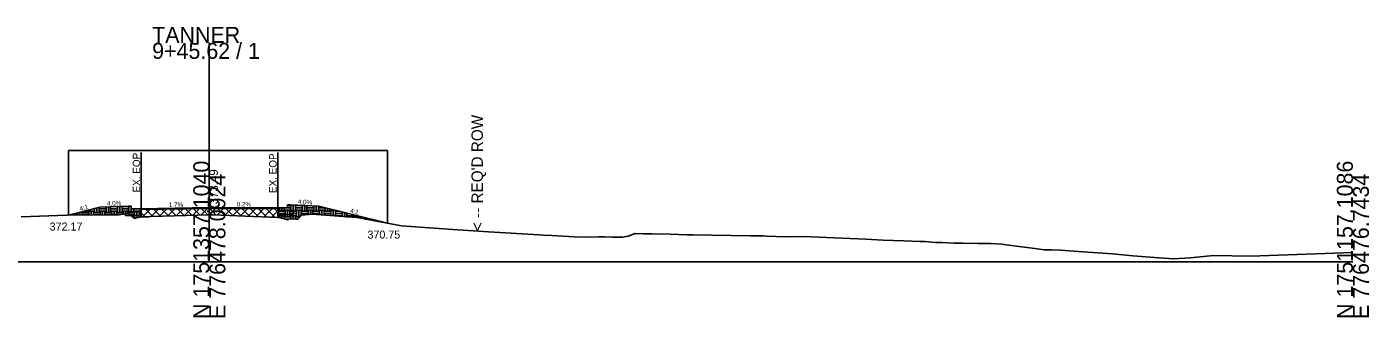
# Model space of a CAD drawing. Extents: x 774192 to 776597, y 1750236 to 1752784.
# Drawn here: x 774851.4 to 775086.2, y 1752248.9 to 1752299.7 of the extents above; entities that cross this region are included whole.
import ezdxf

# ---------------------------------------------------------------- set-up
doc = ezdxf.new("R2010")
doc.units = 0
for name, color, linetype in [('ControlPoints', 7, 'Continuous'), ('Default', 7, 'Continuous'), ('Observations', 7, 'Continuous'), ('Setups', 7, 'Continuous'), ('SHEET_BORDER_TX', 7, 'Continuous'), ('SHEET_DATE_DGN_TX', 7, 'Continuous'), ('SHEET_LOGO', 7, 'Continuous'), ('SHEET_PLOTTING_SHAPE', 7, 'Continuous'), ('SHEET_PRELIM', 7, 'Continuous'), ('SHEET_PROJ_NUMBER', 7, 'Continuous'), ('SHEET_TITLE_BLOCK_TX', 7, 'Continuous'), ('SHEET_WORK_NUMBER', 7, 'Continuous'), ('TS_BACKBONE', 7, 'Continuous'), ('TS_DIMENSIONS', 7, 'Continuous')]:
    doc.layers.add(name, color=color, linetype=linetype)

msp = doc.modelspace()

# ---------------------------------------------------------------- linework, layer by layer
at = {"layer": 'ControlPoints'}
msp.add_lwpolyline([(774850.41, 1752266.46), (774858.47, 1752266.74), (774865.85, 1752266.76), (774867.52, 1752266.78), (774869.22, 1752267.02), (774870.21, 1752266.17), (774871.43, 1752266.43), (774872.71, 1752266.42), (774873.08, 1752266.52), (774883.33, 1752266.76), (774884.02, 1752266.78), (774895.29, 1752266.33), (774895.62, 1752266.32), (774897.13, 1752265.93), (774897.32, 1752266.11), (774898.78, 1752266.03), (774899.42, 1752266.71), (774901.3, 1752266.88), (774909.14, 1752266.3), (774909.18, 1752266.3), (774916.94, 1752264.88), (774922.66, 1752264.44), (774925.93, 1752264.21), (774929.53, 1752263.97), (774932.17, 1752263.84), (774941.04, 1752263.29), (774941.76, 1752263.24), (774943.26, 1752263.18), (774946.18, 1752262.99), (774947.13, 1752262.95), (774949.77, 1752262.89), (774951.45, 1752262.91), (774952.46, 1752262.91), (774953.84, 1752262.9), (774955.55, 1752262.85), (774956.56, 1752263.08), (774957.8, 1752263.51), (774959.24, 1752263.49), (774960.13, 1752263.47), (774960.72, 1752263.46), (774963.93, 1752263.39), (774966.91, 1752263.28), (774967.89, 1752263.27), (774977.89, 1752263.1), (774979.19, 1752263.09), (774980.23, 1752263.09), (774980.8, 1752263.03), (774984.19, 1752262.95), (774987.16, 1752263), (774998.16, 1752262.54), (774999.12, 1752262.48), (775001.19, 1752262.36), (775004.81, 1752262.25), (775007.6, 1752262.13), (775008.5, 1752262.13), (775010.3, 1752261.93), (775011.44, 1752261.93), (775012.46, 1752261.88), (775013.59, 1752261.85), (775015.16, 1752261.82), (775017.82, 1752261.75), (775020.02, 1752261.75), (775021.97, 1752261.64), (775022.28, 1752261.6), (775022.71, 1752261.55), (775027.7, 1752260.9), (775029.35, 1752260.69), (775030.08, 1752260.66), (775030.6, 1752260.65), (775032.23, 1752260.6), (775035.28, 1752260.35), (775041.3, 1752259.95), (775044.86, 1752259.62), (775049.41, 1752259.26), (775052.01, 1752259.08), (775054.85, 1752259.29), (775058.95, 1752259.68), (775065.45, 1752259.56), (775083.33, 1752260.21)], dxfattribs=at)
at = {"layer": 'Default'}
for p, q in [((774871.33, 1752267.69), (774883.34, 1752267.89)), ((774883.33, 1752267.89), (774895.33, 1752267.86))]:
    msp.add_line(p, q, dxfattribs=at)
at = {"layer": 'Setups'}
for p, q in [((774883.33, 1752258.57), (774883.33, 1752296.88)), ((774683.33, 1752258.57), (774883.33, 1752258.57)), ((774883.33, 1752258.57), (775083.33, 1752258.57))]:
    msp.add_line(p, q, dxfattribs=at)
at = {"layer": 'SHEET_BORDER_TX'}
for p, q in [((774868.67, 1752266.64), (774868.67, 1752267.31)), ((774898, 1752266.86), (774898, 1752267.53)), ((774871.35, 1752266.69), (774868.67, 1752266.64)), ((774895.33, 1752266.86), (774898, 1752266.86))]:
    msp.add_line(p, q, dxfattribs=at)
for points in [[(774868.67, 1752267.31), (774871.33, 1752267.35), (774871.35, 1752266.69)], [(774898, 1752267.53), (774895.33, 1752267.53), (774895.33, 1752266.86)]]:
    msp.add_lwpolyline(points, dxfattribs=at)
at = {"layer": 'SHEET_LOGO'}
for p, q in [((774871.43, 1752277.71), (774871.43, 1752266.43)), ((774895.29, 1752277.71), (774895.29, 1752266.33))]:
    msp.add_line(p, q, dxfattribs=at)
at = {"layer": 'SHEET_PLOTTING_SHAPE'}
for p, q in [((774869.17, 1752267.32), (774869.17, 1752268.32)), ((774871.33, 1752267.35), (774869.17, 1752267.32)), ((774871.33, 1752267.85), (774871.33, 1752267.35)), ((774895.33, 1752268.03), (774895.33, 1752267.53)), ((774895.33, 1752267.53), (774897.5, 1752267.53)), ((774897.5, 1752267.53), (774897.5, 1752268.53))]:
    msp.add_line(p, q, dxfattribs=at)
at = {"layer": 'SHEET_PROJ_NUMBER'}
for p, q in [((774858.68, 1752266.74), (774858.68, 1752278.06)), ((774858.68, 1752278.06), (774914.5, 1752278.06)), ((774914.5, 1752278.06), (774914.5, 1752265.33))]:
    msp.add_line(p, q, dxfattribs=at)
at = {"layer": 'SHEET_TITLE_BLOCK_TX'}
for p, q in [((774864.17, 1752268.12), (774858.68, 1752266.74)), ((774869.17, 1752268.32), (774864.17, 1752268.12)), ((774869.67, 1752268.33), (774869.17, 1752268.32)), ((774869.67, 1752267.83), (774869.67, 1752268.33)), ((774871.33, 1752267.85), (774869.67, 1752267.83)), ((774871.33, 1752267.85), (774883.33, 1752268.06)), ((774883.33, 1752268.06), (774895.33, 1752268.03)), ((774895.33, 1752268.03), (774897, 1752268.03)), ((774897, 1752268.03), (774897, 1752268.53)), ((774897, 1752268.53), (774897.5, 1752268.53)), ((774897.5, 1752268.53), (774902.5, 1752268.33)), ((774902.5, 1752268.33), (774914.5, 1752265.33))]:
    msp.add_line(p, q, dxfattribs=at)
at = {"layer": 'SHEET_WORK_NUMBER'}
for p, q in [((774871.33, 1752267.35), (774871.33, 1752266.41)), ((774895.33, 1752267.53), (774895.33, 1752266.33))]:
    msp.add_line(p, q, dxfattribs=at)
msp.add_lwpolyline([(774871.33, 1752266.41), (774871.43, 1752266.43), (774872.71, 1752266.42), (774873.08, 1752266.52), (774883.33, 1752266.76), (774884.02, 1752266.78), (774895.33, 1752266.33)], dxfattribs=at)
at = {"layer": 'TS_BACKBONE'}
for p, q in [((774860.27, 1752267.14), (774860.27, 1752266.75)), ((774860.67, 1752267.24), (774860.67, 1752266.75)), ((774861.07, 1752267.32), (774861.07, 1752266.75)), ((774861.17, 1752267.22), (774862.17, 1752267.22)), ((774861.27, 1752267.39), (774861.27, 1752267.32)), ((774861.67, 1752267.49), (774861.67, 1752267.32)), ((774862.07, 1752267.59), (774862.07, 1752267.32)), ((774862.17, 1752267.42), (774863.17, 1752267.42)), ((774862.27, 1752267.32), (774862.27, 1752266.75)), ((774862.67, 1752267.32), (774862.67, 1752266.75)), ((774863, 1752267.82), (774863.17, 1752267.82)), ((774863.07, 1752267.32), (774863.07, 1752266.75)), ((774863.17, 1752267.22), (774864.17, 1752267.22)), ((774863.27, 1752267.89), (774863.27, 1752267.32)), ((774863.67, 1752267.99), (774863.67, 1752267.32)), ((774864.07, 1752268.09), (774864.07, 1752267.32)), ((774864.17, 1752267.82), (774865.17, 1752267.82)), ((774864.17, 1752267.42), (774865.17, 1752267.42)), ((774864.27, 1752267.32), (774864.27, 1752266.75)), ((774864.67, 1752267.32), (774864.67, 1752266.75)), ((774865.07, 1752267.32), (774865.07, 1752266.76)), ((774865.17, 1752267.22), (774866.17, 1752267.22)), ((774865.27, 1752268.16), (774865.27, 1752267.32)), ((774865.67, 1752268.18), (774865.67, 1752267.32)), ((774866.07, 1752268.19), (774866.07, 1752267.32)), ((774866.17, 1752267.82), (774867.17, 1752267.82)), ((774866.17, 1752267.42), (774867.17, 1752267.42)), ((774866.27, 1752267.32), (774866.27, 1752266.76)), ((774866.67, 1752267.32), (774866.67, 1752266.77)), ((774866.84, 1752268.22), (774867.17, 1752268.22)), ((774867.07, 1752267.32), (774867.07, 1752266.77)), ((774867.17, 1752267.22), (774868.17, 1752267.22)), ((774867.27, 1752268.24), (774867.27, 1752267.32)), ((774867.67, 1752268.26), (774867.67, 1752267.32)), ((774868.07, 1752268.27), (774868.07, 1752267.32)), ((774868.17, 1752268.22), (774869.17, 1752268.22)), ((774868.17, 1752267.82), (774869.17, 1752267.82)), ((774868.17, 1752267.42), (774869.17, 1752267.42)), ((774868.27, 1752267.32), (774868.27, 1752266.89)), ((774868.67, 1752267.32), (774868.67, 1752266.94)), ((774869.07, 1752267.32), (774869.07, 1752267)), ((774869.17, 1752267.22), (774870.17, 1752267.22)), ((774869.27, 1752268.32), (774869.27, 1752267.32)), ((774869.27, 1752267.32), (774869.27, 1752267.32)), ((774869.67, 1752267.83), (774869.67, 1752267.33)), ((774869.67, 1752267.33), (774869.67, 1752267.32)), ((774870.07, 1752267.83), (774870.07, 1752267.33)), ((774870.07, 1752267.33), (774870.07, 1752267.32)), ((774870.17, 1752267.82), (774871.17, 1752267.82)), ((774870.17, 1752267.42), (774871.17, 1752267.42)), ((774870.27, 1752267.32), (774870.27, 1752266.32)), ((774870.67, 1752267.32), (774870.67, 1752266.32)), ((774871.07, 1752267.32), (774871.07, 1752266.36)), ((774871.17, 1752267.22), (774871.33, 1752267.22)), ((774871.27, 1752267.85), (774871.27, 1752267.35)), ((774871.27, 1752267.35), (774871.27, 1752267.32)), ((774871.33, 1752267.52), (774871.67, 1752267.86)), ((774871.33, 1752267.19), (774872.09, 1752266.43)), ((774871.66, 1752266.43), (774873.11, 1752267.88)), ((774872.07, 1752267.87), (774873.41, 1752266.53)), ((774873.17, 1752266.52), (774874.55, 1752267.91)), ((774873.46, 1752267.89), (774874.79, 1752266.56)), ((774874.62, 1752266.56), (774875.99, 1752267.93)), ((774874.85, 1752267.91), (774876.17, 1752266.59)), ((774876.06, 1752266.59), (774877.43, 1752267.96)), ((774876.24, 1752267.94), (774877.55, 1752266.63)), ((774877.51, 1752266.63), (774878.87, 1752267.98)), ((774877.63, 1752267.96), (774878.93, 1752266.66)), ((774878.96, 1752266.66), (774880.31, 1752268.01)), ((774879.02, 1752267.98), (774880.32, 1752266.69)), ((774880.41, 1752266.69), (774881.74, 1752268.03)), ((774880.41, 1752268.01), (774881.7, 1752266.72)), ((774881.8, 1752268.03), (774883.08, 1752266.76)), ((774881.86, 1752266.73), (774883.18, 1752268.06)), ((774883.19, 1752268.06), (774884.49, 1752266.76)), ((774883.3, 1752266.76), (774884.6, 1752268.06)), ((774884.61, 1752268.06), (774885.96, 1752266.7)), ((774884.71, 1752266.75), (774886.01, 1752268.05)), ((774886.03, 1752268.05), (774887.44, 1752266.64)), ((774886.07, 1752266.7), (774887.42, 1752268.05)), ((774887.43, 1752266.64), (774888.83, 1752268.05)), ((774887.44, 1752268.05), (774888.91, 1752266.59)), ((774888.79, 1752266.59), (774890.24, 1752268.04)), ((774888.86, 1752268.05), (774890.38, 1752266.53)), ((774890.15, 1752266.54), (774891.65, 1752268.04)), ((774890.28, 1752268.04), (774891.85, 1752266.47)), ((774891.51, 1752266.48), (774893.06, 1752268.04)), ((774891.7, 1752268.04), (774893.32, 1752266.41)), ((774892.87, 1752266.43), (774894.48, 1752268.03)), ((774893.11, 1752268.04), (774894.8, 1752266.35)), ((774894.23, 1752266.38), (774895.33, 1752267.48)), ((774894.53, 1752268.03), (774895.33, 1752267.23)), ((774895.33, 1752267.63), (774895.5, 1752267.63)), ((774895.4, 1752267.53), (774895.4, 1752267.53)), ((774895.4, 1752267.53), (774895.4, 1752266.53)), ((774895.5, 1752267.43), (774896.5, 1752267.43)), ((774895.61, 1752268.03), (774895.61, 1752267.53)), ((774895.61, 1752267.53), (774895.61, 1752267.53)), ((774896.01, 1752268.03), (774896.01, 1752267.53)), ((774896.01, 1752267.53), (774896.01, 1752267.53)), ((774896.41, 1752268.03), (774896.41, 1752267.53)), ((774896.41, 1752267.53), (774896.41, 1752267.53)), ((774896.5, 1752267.63), (774897.5, 1752267.63)), ((774896.6, 1752267.53), (774896.6, 1752267.53)), ((774896.6, 1752267.53), (774896.6, 1752266.53)), ((774897, 1752268.53), (774897, 1752268.53)), ((774897, 1752268.43), (774897.5, 1752268.43)), ((774897, 1752268.03), (774897.5, 1752268.03)), ((774897, 1752267.53), (774897, 1752267.53)), ((774897, 1752267.53), (774897, 1752266.53)), ((774897.4, 1752268.53), (774897.4, 1752268.53)), ((774897.4, 1752267.53), (774897.4, 1752267.53)), ((774897.4, 1752267.53), (774897.4, 1752266.53)), ((774897.5, 1752267.43), (774898.5, 1752267.43)), ((774897.61, 1752268.52), (774897.61, 1752267.53)), ((774898.01, 1752268.51), (774898.01, 1752267.53)), ((774898.41, 1752268.49), (774898.41, 1752267.53)), ((774898.5, 1752268.43), (774899.5, 1752268.43)), ((774898.5, 1752268.03), (774899.5, 1752268.03)), ((774898.5, 1752267.63), (774899.5, 1752267.63)), ((774898.6, 1752267.53), (774898.6, 1752266.53)), ((774899, 1752267.53), (774899, 1752266.53)), ((774899.4, 1752267.53), (774899.4, 1752266.69)), ((774899.5, 1752267.43), (774900.5, 1752267.43)), ((774899.61, 1752268.44), (774899.61, 1752267.53)), ((774900.01, 1752268.43), (774900.01, 1752267.53)), ((774900.41, 1752268.41), (774900.41, 1752267.53)), ((774900.5, 1752268.03), (774901.5, 1752268.03)), ((774900.5, 1752267.63), (774901.5, 1752267.63)), ((774900.6, 1752267.53), (774900.6, 1752266.82)), ((774901, 1752267.53), (774901, 1752266.86)), ((774901.4, 1752267.53), (774901.4, 1752266.88)), ((774901.5, 1752267.43), (774902.5, 1752267.43)), ((774901.61, 1752268.36), (774901.61, 1752267.53)), ((774902.01, 1752268.35), (774902.01, 1752267.53)), ((774902.41, 1752268.33), (774902.41, 1752267.53)), ((774902.5, 1752268.03), (774903.5, 1752268.03)), ((774902.5, 1752267.63), (774903.5, 1752267.63)), ((774902.6, 1752267.53), (774902.6, 1752266.79)), ((774903, 1752267.53), (774903, 1752266.76)), ((774903.4, 1752267.53), (774903.4, 1752266.73)), ((774903.5, 1752267.43), (774904.5, 1752267.43)), ((774903.61, 1752268.05), (774903.61, 1752267.53)), ((774904.01, 1752267.95), (774904.01, 1752267.53)), ((774904.41, 1752267.85), (774904.41, 1752267.53)), ((774904.5, 1752267.63), (774905.27, 1752267.63)), ((774904.6, 1752267.53), (774904.6, 1752266.64)), ((774905, 1752267.53), (774905, 1752266.61)), ((774905.4, 1752267.53), (774905.4, 1752266.58)), ((774905.5, 1752267.43), (774906.07, 1752267.43)), ((774905.61, 1752267.55), (774905.61, 1752267.53)), ((774906.6, 1752267.3), (774906.6, 1752266.53)), ((774907, 1752267.2), (774907, 1752266.53)), ((774907.4, 1752267.1), (774907.4, 1752266.53)), ((774859.07, 1752266.84), (774859.07, 1752266.75)), ((774859.17, 1752266.82), (774860.17, 1752266.82)), ((774861.17, 1752266.82), (774862.17, 1752266.82)), ((774863.17, 1752266.82), (774864.17, 1752266.82)), ((774865.17, 1752266.82), (774866.17, 1752266.82)), ((774867.17, 1752266.82), (774867.83, 1752266.82)), ((774869.45, 1752266.82), (774870.17, 1752266.82)), ((774869.92, 1752266.42), (774870.17, 1752266.42)), ((774870.07, 1752266.32), (774870.07, 1752266.29)), ((774870.17, 1752266.23), (774870.48, 1752266.23)), ((774871.17, 1752266.82), (774871.33, 1752266.82)), ((774871.17, 1752266.42), (774871.33, 1752266.42)), ((774895.33, 1752266.44), (774895.5, 1752266.44)), ((774895.5, 1752267.03), (774896.5, 1752267.03)), ((774895.5, 1752266.63), (774896.5, 1752266.63)), ((774895.61, 1752266.53), (774895.61, 1752266.32)), ((774896.01, 1752266.53), (774896.01, 1752266.22)), ((774896.41, 1752266.53), (774896.41, 1752266.12)), ((774896.5, 1752266.44), (774897.5, 1752266.44)), ((774896.7, 1752266.04), (774897.25, 1752266.04)), ((774897.5, 1752267.03), (774898.5, 1752267.03)), ((774897.5, 1752266.63), (774898.5, 1752266.63)), ((774897.61, 1752266.53), (774897.61, 1752266.09)), ((774898.01, 1752266.53), (774898.01, 1752266.07)), ((774898.41, 1752266.53), (774898.41, 1752266.05)), ((774898.5, 1752266.44), (774899.17, 1752266.44)), ((774898.52, 1752266.04), (774898.79, 1752266.04)), ((774899.5, 1752267.03), (774900.5, 1752267.03)), ((774901.5, 1752267.03), (774902.5, 1752267.03)), ((774903.5, 1752267.03), (774904.5, 1752267.03)), ((774905.5, 1752267.03), (774906.5, 1752267.03)), ((774905.5, 1752266.63), (774906.5, 1752266.63)), ((774906.41, 1752266.53), (774906.41, 1752266.5)), ((774907.27, 1752266.44), (774907.5, 1752266.44)), ((774907.5, 1752267.03), (774907.67, 1752267.03)), ((774907.5, 1752266.63), (774908.5, 1752266.63)), ((774907.61, 1752266.53), (774907.61, 1752266.42)), ((774908.01, 1752266.53), (774908.01, 1752266.39)), ((774908.41, 1752266.53), (774908.41, 1752266.36)), ((774908.5, 1752266.44), (774909.5, 1752266.44)), ((774908.6, 1752266.8), (774908.6, 1752266.53)), ((774909, 1752266.7), (774909, 1752266.53)), ((774909.4, 1752266.6), (774909.4, 1752266.53)), ((774909.61, 1752266.53), (774909.61, 1752266.22)), ((774910.01, 1752266.45), (774910.01, 1752266.15)), ((774910.41, 1752266.35), (774910.41, 1752266.07)), ((774910.59, 1752266.04), (774911.5, 1752266.04)), ((774911.61, 1752266.05), (774911.61, 1752265.85)), ((774912.01, 1752265.95), (774912.01, 1752265.78)), ((774912.41, 1752265.85), (774912.41, 1752265.71)), ((774912.78, 1752265.64), (774913.25, 1752265.64)), ((774913.4, 1752265.54), (774913.4, 1752265.53)), ((774913.61, 1752265.55), (774913.61, 1752265.53)), ((774913.88, 1752265.44), (774914.05, 1752265.44))]:
    msp.add_line(p, q, dxfattribs=at)

# ---------------------------------------------------------------- texts
at = {"layer": 'Observations'}
for s, p in [('372.17', (774855.4, 1752264.04)), ('370.75', (774910.99, 1752262.63))]:
    msp.add_text(s, height=1.4, dxfattribs=at).set_placement(p)
at = {"layer": 'Setups'}
for s, p in [('TANNER', (774873.33, 1752296.88)), ('9+45.62 / 1', (774873.33, 1752294.08))]:
    msp.add_text(s, height=2.8, dxfattribs=at).set_placement(p)
for s, p in [('N 1751357.1040', (774883.33, 1752248.57)), ('N 1751157.1086', (775083.33, 1752248.57)), ('E 776478.0924', (774886.13, 1752248.57)), ('E 776476.7434', (775086.13, 1752248.57))]:
    msp.add_text(s, height=2.8, rotation=90, dxfattribs=at).set_placement(p)
at = {"layer": 'SHEET_DATE_DGN_TX'}
for s, rotation, p in [('4.0%', 357.7094, (774898.79, 1752268.68)), ('4:1', 14.0362, (774860.72, 1752267.46)), ('4.0%', 2.2906, (774865.44, 1752268.37)), ('1.7%', 0.9765, (774876.24, 1752268.14)), ('0.2%', 359.8729, (774888.11, 1752268.25)), ('4:1', 345.9638, (774907.89, 1752267.19))]:
    msp.add_text(s, height=0.8, rotation=rotation, dxfattribs=at).set_placement(p)
at = {"layer": 'SHEET_LOGO'}
for p in [(774871.23, 1752270.69), (774895.09, 1752270.59)]:
    msp.add_text('EX. EOP', height=1.3, rotation=90, dxfattribs=at).set_placement(p)
at = {"layer": 'SHEET_PRELIM'}
msp.add_text(' 373.49', height=1.5, rotation=90, dxfattribs=at).set_placement((774884.83, 1752268.06))
at = {"layer": 'TS_DIMENSIONS'}
msp.add_text("< -- REQ'D ROW", height=2, rotation=90, dxfattribs=at).set_placement((774931.18, 1752263.94))

doc.saveas('drawing.dxf')
